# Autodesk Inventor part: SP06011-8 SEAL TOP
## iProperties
Created: 2012-06
Part Number: SP06011-8 SEAL TOP
Document SubType Name: Modeling
Designer: Administrator
Density: 1 g/cm^3
Stock Number: 21.9521/1  1/16" Aluminum Sheet Anodized
Author: Administrator
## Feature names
1. Extrusion1
2. Hole1
3. Fillet1
